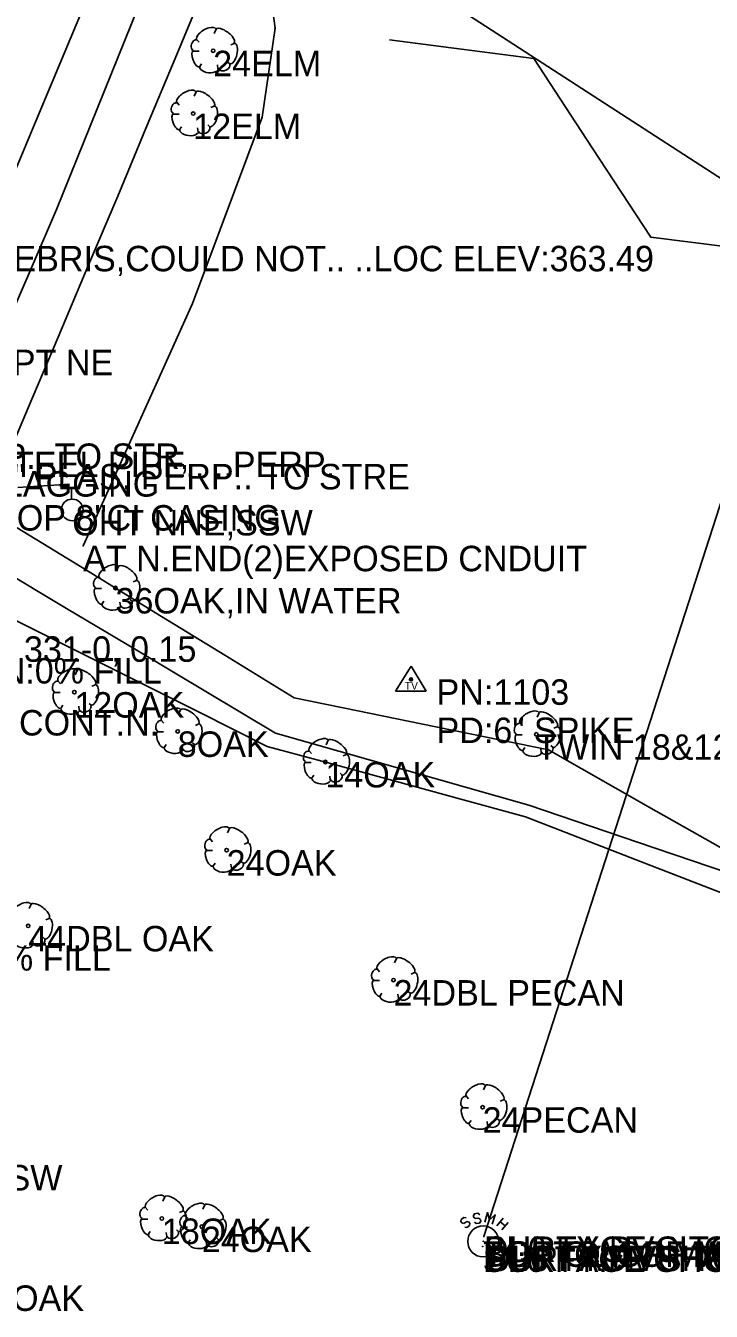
# Model space of a CAD drawing. Extents: x 997398 to 1003416, y 334596 to 337085.
# Drawn here: x 999369.2 to 999503.6, y 335666.7 to 335918.9 of the extents above; entities that cross this region are included whole.
import ezdxf

# ---------------------------------------------------------------- set-up
doc = ezdxf.new("R2010")
doc.units = 0
for name, color, linetype in [('S_EDGE_PAVEMENT', 7, 'Continuous'), ('S_FENCE_ANNOT', 7, 'Continuous'), ('S_FIBER_OPTIC_CABLE', 7, 'Continuous'), ('S_FIBER_OPTIC_CABLE_ANNOT', 7, 'Continuous'), ('S_GRD_PT_SYM', 7, 'Continuous'), ('S_HIST_HIGH_WATER_ANNOT', 7, 'Continuous'), ('S_IRON_PIN_ANNOT', 7, 'Continuous'), ('S_MANHOLE_ANNOT', 7, 'Continuous'), ('S_MISC_TOPO_POINT', 7, 'Continuous'), ('S_PAVEMENT_CROWN', 7, 'Continuous'), ('S_SANITARY_SEWER', 7, 'Continuous'), ('S_SANITARY_SEWER_ANNOT', 7, 'Continuous'), ('S_SECONDARY_CTL', 7, 'Continuous'), ('S_SECONDARY_CTL_ANNOT', 7, 'Continuous'), ('S_SIDE_DRAIN_ANNOT', 7, 'Continuous'), ('S_STREAM', 7, 'Continuous'), ('S_SURVEY_TEXT_ANNOT', 7, 'Continuous'), ('S_TREE', 7, 'Continuous'), ('S_TREE_ANNOT', 7, 'Continuous'), ('S_UTILITY_POLE', 7, 'Continuous'), ('S_UTILITY_POLE_ANNOT', 7, 'Continuous'), ('S_UTL_PT_SYM', 7, 'Continuous'), ('S_WALL', 7, 'Continuous')]:
    doc.layers.add(name, color=color, linetype=linetype)

msp = doc.modelspace()

# ---------------------------------------------------------------- linework, layer by layer
at = {"layer": 'S_EDGE_PAVEMENT'}
for points in [[(999345.79, 335839.7), (999350.09, 335849.94), (999355.27, 335862.25), (999360.45, 335874.56), (999365.63, 335886.87), (999371.17, 335900.18), (999376.72, 335913.48), (999382.27, 335926.79), (999387.81, 335940.1), (999394.44, 335955.02), (999401.06, 335969.95), (999407.69, 335984.87), (999414.31, 335999.8)], [(999431.8, 335993.95), (999426.44, 335980.73), (999421.08, 335967.51), (999415.72, 335954.3), (999410.36, 335941.08), (999404.58, 335927.18), (999398.8, 335913.28), (999393.01, 335899.39), (999387.23, 335885.49), (999381.38, 335871.65), (999375.53, 335857.81), (999369.68, 335843.97), (999364.6, 335831.95)]]:
    msp.add_lwpolyline(points, dxfattribs=at)
at = {"layer": 'S_FIBER_OPTIC_CABLE'}
for p, q in [((999418.06, 335918.42), (999416.18, 335933.11)), ((999415.54, 335900.98), (999418.06, 335918.42)), ((999401.89, 335864.42), (999415.54, 335900.98)), ((999387.01, 335831.35), (999401.89, 335864.42)), ((999380.44, 335816.88), (999387.01, 335831.35))]:
    msp.add_line(p, q, dxfattribs=at)
at = {"layer": 'S_GRD_PT_SYM'}
for points in [[(999458.79, 335679.4), (999458.79, 335679.45), (999458.79, 335679.4), (999458.74, 335679.4), (999458.79, 335679.4), (999458.79, 335679.35), (999458.79, 335679.4), (999458.84, 335679.4)], [(999459, 335681.35), (999459, 335681.4), (999459, 335681.35), (999458.95, 335681.35), (999459, 335681.35), (999459, 335681.3), (999459, 335681.35), (999459.05, 335681.35)], [(999459.5, 335679.55), (999459.5, 335679.6), (999459.5, 335679.55), (999459.45, 335679.55), (999459.5, 335679.55), (999459.5, 335679.5), (999459.5, 335679.55), (999459.55, 335679.55)]]:
    msp.add_lwpolyline(points, dxfattribs=at)
at = {"layer": 'S_PAVEMENT_CROWN'}
msp.add_lwpolyline([(999354.98, 335835.91), (999359.04, 335845.32), (999364.44, 335857.84), (999369.84, 335870.36), (999375.24, 335882.88), (999380.6, 335896.16), (999385.95, 335909.44), (999391.31, 335922.72), (999396.66, 335936.01), (999402.74, 335950.26), (999408.82, 335964.51), (999414.9, 335978.77), (999420.98, 335993.02)], dxfattribs=at)
at = {"layer": 'S_SANITARY_SEWER'}
for p, q in [((999358.9, 335984.04), (999521.53, 335878.51)), ((999459, 335681.35), (999522.12, 335877.02)), ((999454.57, 335684.69), (999454.49, 335684.31)), ((999455.11, 335685.08), (999454.57, 335684.69)), ((999455.54, 335685), (999455.11, 335685.08)), ((999461.54, 335683.45), (999462.78, 335684.93)), ((999454.49, 335684.31), (999454.69, 335684.04)), ((999454.69, 335684.04), (999455.11, 335683.92)), ((999455.11, 335683.92), (999455.65, 335684.27)), ((999455.65, 335683.11), (999455.27, 335683.18)), ((999455.65, 335684.27), (999456.12, 335684.19)), ((999456.2, 335683.49), (999455.65, 335683.11)), ((999456.12, 335684.19), (999456.27, 335683.92)), ((999456.27, 335683.92), (999456.2, 335683.49)), ((999462.2, 335684.23), (999463.17, 335683.42)), ((999463.75, 335684.11), (999462.51, 335682.64))]:
    msp.add_line(p, q, dxfattribs=at)
for points in [[(999458.21, 335685.62), (999457.86, 335685.9), (999457.2, 335685.82), (999456.97, 335685.47), (999457.01, 335685.16), (999457.36, 335684.85), (999457.98, 335684.97), (999458.37, 335684.66), (999458.41, 335684.35), (999458.13, 335683.96), (999457.51, 335683.88), (999457.17, 335684.15)], [(999460.65, 335683.76), (999461.2, 335685.62), (999460.15, 335684.62), (999459.76, 335686.05), (999459.22, 335684.19)]]:
    msp.add_lwpolyline(points, dxfattribs=at)
msp.add_circle((999458.9, 335680.39), 3.05, dxfattribs=at)
at = {"layer": 'S_SECONDARY_CTL'}
for p, q in [((999444.73, 335793.28), (999441.72, 335788.32)), ((999444.73, 335793.28), (999447.67, 335788.32)), ((999441.72, 335788.32), (999447.67, 335788.32))]:
    msp.add_line(p, q, dxfattribs=at)
for radius in [0.311, 0.183, 0.103]:
    msp.add_circle((999444.73, 335790.67), radius, dxfattribs=at)
at = {"layer": 'S_STREAM'}
for points in [[(999331.89, 335832.2), (999349.69, 335826.31), (999367.5, 335820.43), (999381.08, 335812.09), (999394.65, 335803.75), (999408.23, 335795.41), (999421.81, 335787.07), (999434.28, 335784.52), (999446.75, 335781.96), (999459.22, 335779.4), (999471.69, 335776.85), (999491.33, 335765.68), (999510.96, 335754.51)], [(999325.68, 335825.18), (999344.61, 335818.97), (999363.54, 335812.75), (999377.19, 335804.59), (999390.85, 335796.43), (999404.51, 335788.27), (999418.17, 335780.11), (999430.58, 335776.57), (999442.99, 335773.03), (999455.4, 335769.5), (999467.81, 335765.96), (999489.15, 335758.72), (999510.5, 335751.47)], [(999363.15, 335804.23), (999376.49, 335797.55), (999389.84, 335790.87), (999403.19, 335784.2), (999416.53, 335777.52), (999429.2, 335774.06), (999441.86, 335770.61), (999454.53, 335767.16), (999467.19, 335763.7), (999487.73, 335755.71), (999508.28, 335747.72)]]:
    msp.add_lwpolyline(points, dxfattribs=at)
at = {"layer": 'S_TREE'}
for p, q in [((999406.49, 335918.25), (999406.1, 335917.4)), ((999402.69, 335916.24), (999403.2, 335915.66)), ((999410.06, 335915.46), (999409.4, 335915.19)), ((999402.03, 335913.91), (999403.16, 335913.91)), ((999403.2, 335910.74), (999403.66, 335911.43)), ((999409.28, 335911.36), (999408.82, 335911.78)), ((999406.88, 335910.46), (999406.8, 335911.24)), ((999398.78, 335903.91), (999399.29, 335903.32)), ((999402.58, 335905.92), (999402.19, 335905.07)), ((999398.12, 335901.58), (999399.25, 335901.58)), ((999406.15, 335903.13), (999405.49, 335902.86)), ((999399.29, 335898.4), (999399.75, 335899.1)), ((999402.97, 335898.13), (999402.89, 335898.91)), ((999405.37, 335899.02), (999404.91, 335899.45)), ((999383.54, 335810.82), (999384.05, 335810.24)), ((999387.34, 335812.83), (999386.95, 335811.98)), ((999382.89, 335808.49), (999384.01, 335808.49)), ((999390.91, 335810.04), (999390.25, 335809.77)), ((999384.05, 335805.32), (999384.51, 335806.01)), ((999387.73, 335805.04), (999387.65, 335805.82)), ((999390.13, 335805.94), (999389.67, 335806.36)), ((999375.47, 335790.39), (999375.97, 335789.81)), ((999379.27, 335792.4), (999378.88, 335791.55)), ((999374.81, 335788.06), (999375.94, 335788.06)), ((999382.83, 335789.61), (999382.17, 335789.34)), ((999375.97, 335784.89), (999376.44, 335785.58)), ((999379.66, 335784.61), (999379.58, 335785.39)), ((999382.06, 335785.51), (999381.59, 335785.93)), ((999399.54, 335784.7), (999399.15, 335783.84)), ((999469.85, 335784.13), (999469.46, 335783.27)), ((999395.09, 335780.36), (999396.21, 335780.36)), ((999395.74, 335782.68), (999396.25, 335782.1)), ((999403.11, 335781.91), (999402.45, 335781.63)), ((999466.05, 335782.11), (999466.56, 335781.53)), ((999473.41, 335781.34), (999472.76, 335781.07)), ((999396.25, 335777.18), (999396.71, 335777.88)), ((999402.33, 335777.8), (999401.87, 335778.22)), ((999428.49, 335778.71), (999428.1, 335777.85)), ((999465.39, 335779.79), (999466.52, 335779.79)), ((999399.93, 335776.91), (999399.85, 335777.68)), ((999424.69, 335776.69), (999425.2, 335776.11)), ((999432.06, 335775.92), (999431.4, 335775.64)), ((999466.56, 335776.61), (999467.02, 335777.31)), ((999470.24, 335776.34), (999470.16, 335777.11)), ((999472.64, 335777.23), (999472.17, 335777.66)), ((999424.04, 335774.37), (999425.16, 335774.37)), ((999425.2, 335771.19), (999425.66, 335771.89)), ((999428.88, 335770.92), (999428.8, 335771.69)), ((999431.28, 335771.81), (999430.82, 335772.23)), ((999409.12, 335761.41), (999408.74, 335760.55)), ((999405.33, 335759.39), (999405.83, 335758.81)), ((999412.69, 335758.62), (999412.03, 335758.34)), ((999404.67, 335757.07), (999405.79, 335757.07)), ((999405.83, 335753.89), (999406.3, 335754.59)), ((999409.51, 335753.62), (999409.43, 335754.39)), ((999411.91, 335754.51), (999411.45, 335754.93)), ((999370.22, 335746.54), (999369.83, 335745.69)), ((999373.78, 335743.75), (999373.12, 335743.48)), ((999373.01, 335739.64), (999372.54, 335740.07)), ((999370.61, 335738.75), (999370.53, 335739.53)), ((999441.86, 335735.91), (999441.47, 335735.05)), ((999438.06, 335733.89), (999438.57, 335733.31)), ((999445.42, 335733.12), (999444.77, 335732.85)), ((999437.4, 335731.57), (999438.53, 335731.57)), ((999438.57, 335728.39), (999439.03, 335729.09)), ((999442.25, 335728.12), (999442.17, 335728.89)), ((999444.65, 335729.01), (999444.18, 335729.44)), ((999459.33, 335710.96), (999458.94, 335710.11)), ((999455.53, 335708.94), (999456.03, 335708.36)), ((999462.89, 335708.17), (999462.23, 335707.9)), ((999454.87, 335706.62), (999456, 335706.62)), ((999456.03, 335703.44), (999456.5, 335704.14)), ((999459.72, 335703.17), (999459.64, 335703.94)), ((999462.12, 335704.06), (999461.65, 335704.49)), ((999392.63, 335687.11), (999393.13, 335686.53)), ((999396.43, 335689.12), (999396.04, 335688.27)), ((999404.27, 335687.54), (999403.88, 335686.69)), ((999391.97, 335684.78), (999393.1, 335684.78)), ((999399.99, 335686.33), (999399.33, 335686.06)), ((999400.47, 335685.52), (999400.97, 335684.94)), ((999407.83, 335684.75), (999407.17, 335684.48)), ((999393.13, 335681.61), (999393.6, 335682.3)), ((999396.82, 335681.33), (999396.74, 335682.11)), ((999399.22, 335682.23), (999398.75, 335682.65)), ((999399.81, 335683.2), (999400.93, 335683.2)), ((999400.97, 335680.02), (999401.44, 335680.72)), ((999404.65, 335679.75), (999404.58, 335680.52)), ((999407.06, 335680.64), (999406.59, 335681.07))]:
    msp.add_line(p, q, dxfattribs=at)
msp.add_lwpolyline([(999523.83, 335779.4), (999527.91, 335799.55), (999531.98, 335819.7), (999541.56, 335835.34), (999551.14, 335850.97), (999533.12, 335862.72), (999515.1, 335874.46), (999491.75, 335877.42), (999480.27, 335894.95), (999468.8, 335912.48), (999454.65, 335914.32), (999440.5, 335916.16)], dxfattribs=at)
for centre in [(999405.93, 335914.01), (999402.02, 335901.68), (999386.78, 335808.59), (999378.71, 335788.16), (999398.98, 335780.45), (999469.29, 335779.88), (999427.93, 335774.46), (999408.57, 335757.16), (999369.66, 335742.29), (999441.3, 335731.66), (999458.77, 335706.71), (999395.87, 335684.88), (999403.71, 335683.29)]:
    msp.add_circle(centre, 0.341, dxfattribs=at)
for centre, major_axis, ratio, start_param, end_param in [((999404.6, 335917.21), (1.86, 1.08), 0.471018, 0, 3.141593), ((999408.25, 335916.89), (-1.81, 1.36), 0.405113, 3.141593, 6.283186), ((999402.36, 335915.09), (0.31, 1.03), 0.646762, 0, 3.141593), ((999402.67, 335912.44), (-0.61, 1.6), 0.420543, 6.283185, 9.424777), ((999409.61, 335913.48), (0.46, 2.04), 0.482994, 3.141593, 6.283185), ((999408.08, 335910.96), (1.09, 0.46), 0.711534, 3.141592, 6.283185), ((999405.13, 335910.66), (-1.83, 0.19), 0.529943, 0, 3.141593), ((999400.69, 335904.88), (1.86, 1.08), 0.471018, 0, 3.141593), ((999398.45, 335902.76), (0.31, 1.03), 0.646762, 0, 3.141593), ((999404.34, 335904.55), (-1.81, 1.36), 0.405113, 3.141593, 6.283186), ((999398.76, 335900.11), (-0.61, 1.6), 0.420543, 6.283185, 9.424777), ((999405.7, 335901.15), (0.46, 2.04), 0.482994, 3.141593, 6.283185), ((999404.17, 335898.62), (1.09, 0.46), 0.711534, 3.141592, 6.283185), ((999401.22, 335898.33), (-1.83, 0.19), 0.529943, 0, 3.141593), ((999385.45, 335811.79), (1.86, 1.08), 0.471018, 0, 3.141593), ((999389.1, 335811.47), (-1.81, 1.36), 0.405113, 3.141593, 6.283186), ((999383.21, 335809.68), (0.31, 1.03), 0.646762, 0, 3.141593), ((999383.52, 335807.02), (-0.61, 1.6), 0.420543, 6.283185, 9.424777), ((999390.46, 335808.06), (0.46, 2.04), 0.482994, 3.141593, 6.283185), ((999388.94, 335805.54), (1.09, 0.46), 0.711534, 3.141592, 6.283185), ((999385.98, 335805.24), (-1.83, 0.19), 0.529943, 0, 3.141593), ((999377.37, 335791.36), (1.86, 1.08), 0.471018, 0, 3.141593), ((999375.14, 335789.25), (0.31, 1.03), 0.646762, 0, 3.141593), ((999381.03, 335791.04), (-1.81, 1.36), 0.405113, 3.141593, 6.283186), ((999375.44, 335786.59), (-0.61, 1.6), 0.420543, 6.283185, 9.424777), ((999382.38, 335787.63), (0.46, 2.04), 0.482994, 3.141593, 6.283185), ((999380.86, 335785.11), (1.09, 0.46), 0.711534, 3.141592, 6.283185), ((999377.9, 335784.81), (-1.83, 0.19), 0.529943, 0, 3.141593), ((999397.65, 335783.65), (1.86, 1.08), 0.471018, 0, 3.141593), ((999401.3, 335783.33), (-1.81, 1.36), 0.405113, 3.141593, 6.283186), ((999467.95, 335783.08), (1.86, 1.08), 0.471018, 0, 3.141593), ((999471.61, 335782.76), (-1.81, 1.36), 0.405113, 3.141593, 6.283186), ((999395.41, 335781.54), (0.31, 1.03), 0.646762, 0, 3.141593), ((999395.72, 335778.89), (-0.61, 1.6), 0.420543, 6.283185, 9.424777), ((999402.66, 335779.92), (0.46, 2.04), 0.482994, 3.141593, 6.283185), ((999465.72, 335780.97), (0.31, 1.03), 0.646762, 0, 3.141593), ((999472.96, 335779.35), (0.46, 2.04), 0.482994, 3.141593, 6.283185), ((999401.14, 335777.4), (1.09, 0.46), 0.711534, 3.141592, 6.283185), ((999426.6, 335777.66), (1.86, 1.08), 0.471018, 0, 3.141593), ((999430.25, 335777.34), (-1.81, 1.36), 0.405113, 3.141593, 6.283186), ((999466.03, 335778.32), (-0.61, 1.6), 0.420543, 6.283185, 9.424777), ((999398.18, 335777.11), (-1.83, 0.19), 0.529943, 0, 3.141593), ((999424.36, 335775.55), (0.31, 1.03), 0.646762, 0, 3.141593), ((999431.61, 335773.93), (0.46, 2.04), 0.482994, 3.141593, 6.283185), ((999468.49, 335776.54), (-1.83, 0.19), 0.529943, 0, 3.141593), ((999471.44, 335776.83), (1.09, 0.46), 0.711534, 3.141592, 6.283185), ((999424.67, 335772.9), (-0.61, 1.6), 0.420543, 6.283185, 9.424777), ((999427.13, 335771.12), (-1.83, 0.19), 0.529943, 0, 3.141593), ((999430.09, 335771.41), (1.09, 0.46), 0.711534, 3.141592, 6.283185), ((999407.23, 335760.36), (1.86, 1.08), 0.471018, 0, 3.141593), ((999410.88, 335760.04), (-1.81, 1.36), 0.405113, 3.141593, 6.283186), ((999405, 335758.25), (0.31, 1.03), 0.646762, 0, 3.141593), ((999412.24, 335756.63), (0.46, 2.04), 0.482994, 3.141593, 6.283185), ((999405.3, 335755.6), (-0.61, 1.6), 0.420543, 6.283185, 9.424777), ((999407.76, 335753.82), (-1.83, 0.19), 0.529943, 0, 3.141593), ((999410.72, 335754.11), (1.09, 0.46), 0.711534, 3.141592, 6.283185), ((999368.32, 335745.5), (1.86, 1.08), 0.471018, 0, 3.141593), ((999371.98, 335745.17), (-1.81, 1.36), 0.405113, 3.141593, 6.283186), ((999373.33, 335741.76), (0.46, 2.04), 0.482994, 3.141593, 6.283185), ((999368.86, 335738.95), (-1.83, 0.19), 0.529943, 0, 3.141593), ((999371.81, 335739.24), (1.09, 0.46), 0.711534, 3.141592, 6.283185), ((999439.97, 335734.86), (1.86, 1.08), 0.471018, 0, 3.141593), ((999443.62, 335734.54), (-1.81, 1.36), 0.405113, 3.141593, 6.283186), ((999437.73, 335732.75), (0.31, 1.03), 0.646762, 0, 3.141593), ((999444.98, 335731.13), (0.46, 2.04), 0.482994, 3.141593, 6.283185), ((999438.04, 335730.1), (-0.61, 1.6), 0.420543, 6.283185, 9.424777), ((999440.5, 335728.32), (-1.83, 0.19), 0.529943, 0, 3.141593), ((999443.45, 335728.61), (1.09, 0.46), 0.711534, 3.141592, 6.283185), ((999457.43, 335709.91), (1.86, 1.08), 0.471018, 0, 3.141593), ((999461.09, 335709.59), (-1.81, 1.36), 0.405113, 3.141593, 6.283186), ((999455.2, 335707.8), (0.31, 1.03), 0.646762, 0, 3.141593), ((999462.44, 335706.18), (0.46, 2.04), 0.482994, 3.141593, 6.283185), ((999455.5, 335705.15), (-0.61, 1.6), 0.420543, 6.283185, 9.424777), ((999457.97, 335703.37), (-1.83, 0.19), 0.529943, 0, 3.141593), ((999460.92, 335703.66), (1.09, 0.46), 0.711534, 3.141592, 6.283185), ((999394.53, 335688.08), (1.86, 1.08), 0.471018, 0, 3.141593), ((999398.19, 335687.76), (-1.81, 1.36), 0.405113, 3.141593, 6.283186), ((999392.3, 335685.96), (0.31, 1.03), 0.646762, 0, 3.141593), ((999402.37, 335686.49), (1.86, 1.08), 0.471018, 0, 3.141593), ((999406.03, 335686.17), (-1.81, 1.36), 0.405113, 3.141593, 6.283186), ((999392.61, 335683.31), (-0.61, 1.6), 0.420543, 6.283185, 9.424777), ((999399.54, 335684.35), (0.46, 2.04), 0.482994, 3.141593, 6.283185), ((999400.14, 335684.38), (0.31, 1.03), 0.646762, 0, 3.141593), ((999407.38, 335682.76), (0.46, 2.04), 0.482994, 3.141593, 6.283185), ((999398.02, 335681.83), (1.09, 0.46), 0.711534, 3.141592, 6.283185), ((999400.44, 335681.73), (-0.61, 1.6), 0.420543, 6.283185, 9.424777), ((999395.07, 335681.53), (-1.83, 0.19), 0.529943, 0, 3.141593), ((999402.9, 335679.95), (-1.83, 0.19), 0.529943, 0, 3.141593), ((999405.86, 335680.24), (1.09, 0.46), 0.711534, 3.141592, 6.283185)]:
    msp.add_ellipse(centre, major_axis=major_axis, ratio=ratio, start_param=start_param, end_param=end_param, dxfattribs=at)
at = {"layer": 'S_UTILITY_POLE'}
msp.add_line((999378.16, 335826.04), (999378.16, 335828.15), dxfattribs=at)
msp.add_circle((999378.29, 335823.9), 2.13, dxfattribs=at)
at = {"layer": 'S_UTL_PT_SYM'}
for points in [[(999418.06, 335918.42), (999418.06, 335918.47), (999418.06, 335918.42), (999418.01, 335918.42), (999418.06, 335918.42), (999418.06, 335918.37), (999418.06, 335918.42), (999418.11, 335918.42)], [(999415.54, 335900.98), (999415.54, 335901.03), (999415.54, 335900.98), (999415.49, 335900.98), (999415.54, 335900.98), (999415.54, 335900.93), (999415.54, 335900.98), (999415.59, 335900.98)], [(999401.89, 335864.42), (999401.89, 335864.47), (999401.89, 335864.42), (999401.84, 335864.42), (999401.89, 335864.42), (999401.89, 335864.37), (999401.89, 335864.42), (999401.94, 335864.42)], [(999387.01, 335831.35), (999387.01, 335831.4), (999387.01, 335831.35), (999386.96, 335831.35), (999387.01, 335831.35), (999387.01, 335831.3), (999387.01, 335831.35), (999387.06, 335831.35)], [(999380.44, 335816.88), (999380.44, 335816.93), (999380.44, 335816.88), (999380.39, 335816.88), (999380.44, 335816.88), (999380.44, 335816.83), (999380.44, 335816.88), (999380.49, 335816.88)], [(999458.79, 335679.4), (999458.79, 335679.45), (999458.79, 335679.4), (999458.74, 335679.4), (999458.79, 335679.4), (999458.79, 335679.35), (999458.79, 335679.4), (999458.84, 335679.4)], [(999458.9, 335680.39), (999458.9, 335680.44), (999458.9, 335680.39), (999458.85, 335680.39), (999458.9, 335680.39), (999458.9, 335680.34), (999458.9, 335680.39), (999458.95, 335680.39)], [(999459, 335681.35), (999459, 335681.4), (999459, 335681.35), (999458.95, 335681.35), (999459, 335681.35), (999459, 335681.3), (999459, 335681.35), (999459.05, 335681.35)], [(999459.5, 335679.55), (999459.5, 335679.6), (999459.5, 335679.55), (999459.45, 335679.55), (999459.5, 335679.55), (999459.5, 335679.5), (999459.5, 335679.55), (999459.55, 335679.55)]]:
    msp.add_lwpolyline(points, dxfattribs=at)
at = {"layer": 'S_WALL'}
msp.add_lwpolyline([(999367.62, 335828.3), (999377.79, 335828.97)], dxfattribs=at)

# ---------------------------------------------------------------- texts
at = {"layer": 'S_FENCE_ANNOT'}
msp.add_text('JOINS ANGLE PT NE', height=5, dxfattribs=at).set_placement((999320.58, 335850.35))
at = {"layer": 'S_FIBER_OPTIC_CABLE_ANNOT'}
for s, p in [('AT N.END(2)EXPOSED CNDUIT', (999380.44, 335811.88)), ('CONT.N.', (999367.86, 335779.65))]:
    msp.add_text(s, height=5, dxfattribs=at).set_placement(p)
at = {"layer": 'S_HIST_HIGH_WATER_ANNOT'}
msp.add_text('TOP OF DEBRIS,COULD NOT.. ..LOC ELEV:363.49', height=5, dxfattribs=at).set_placement((999335.19, 335870.73))
at = {"layer": 'S_IRON_PIN_ANNOT'}
msp.add_text('TPOST W/ FLAGGING', height=5, dxfattribs=at).set_placement((999326.64, 335826.52))
at = {"layer": 'S_MANHOLE_ANNOT'}
msp.add_text('BOTTOM OF MANHOLE', height=5, dxfattribs=at).set_placement((999458.9, 335675.39))
at = {"layer": 'S_MISC_TOPO_POINT'}
for p in [(999458.79, 335674.4), (999459, 335676.35), (999459.5, 335674.55)]:
    msp.add_text('SURFACE SHOT FOR UG PIPE', height=5, dxfattribs=at).set_placement(p)
at = {"layer": 'S_SANITARY_SEWER_ANNOT'}
for s, p in [('TOP CL OF MANHOLE', (999458.9, 335675.39)), ('DI:6 TY:PVC', (999458.79, 335674.4)), ('DI:6 TY:PVC TO NNE', (999459, 335676.35)), ('DI:6 TY:PVC TO SE', (999459.5, 335674.55))]:
    msp.add_text(s, height=5, dxfattribs=at).set_placement(p)
at = {"layer": 'S_SECONDARY_CTL'}
msp.add_text('TV', height=1.5, rotation=360, dxfattribs=at).set_placement((999443.52, 335788.66))
at = {"layer": 'S_SECONDARY_CTL_ANNOT'}
for s, p in [('PN:1103', (999449.73, 335785.67)), ('PD:6" SPIKE', (999449.73, 335778.17))]:
    msp.add_text(s, height=5, dxfattribs=at).set_placement(p)
at = {"layer": 'S_SIDE_DRAIN_ANNOT'}
for s, p in [('DI:15 TY:CMP CN:0% FILL', (999314.48, 335789.85)), ('DI:26 DI:24 TY:CPP CN:0% FILL', (999287.77, 335733.51))]:
    msp.add_text(s, height=5, dxfattribs=at).set_placement(p)
at = {"layer": 'S_SURVEY_TEXT_ANNOT'}
for s, p in [('TOP 12"CI CASING,PERP.. TO STR,', (999289.63, 335831.95)), ('EXPOSED 3" STEEL PIPE.. ..PERP.', (999320.1, 335830.34)), ('EXPOSED 3" PLAS, PERP.. TO STRE', (999328.8, 335827.94)), ('TOP 8"CI CASING TOP 8"CI CASING', (999305.61, 335819.86)), ('SN: 331-0, 0.15', (999355.82, 335794.11))]:
    msp.add_text(s, height=5, dxfattribs=at).set_placement(p)
at = {"layer": 'S_TREE_ANNOT'}
for s, p in [('24ELM', (999405.93, 335909.01)), ('12ELM', (999402.02, 335896.68)), ('36OAK,IN WATER', (999386.78, 335803.59)), ('12OAK', (999378.71, 335783.16)), ('8OAK', (999398.98, 335775.45)), ('TWIN 18&12OAK', (999469.29, 335774.88)), ('14OAK', (999427.93, 335769.46)), ('24OAK', (999408.57, 335752.16)), ('44DBL OAK', (999369.66, 335737.29)), ('24DBL PECAN', (999441.3, 335726.66)), ('24PECAN', (999458.77, 335701.71)), ('18OAK', (999395.87, 335679.88)), ('24OAK', (999403.71, 335678.29)), ('36OAK', (999359.06, 335666.75))]:
    msp.add_text(s, height=5, dxfattribs=at).set_placement(p)
at = {"layer": 'S_UTILITY_POLE_ANNOT'}
for p in [(999378.29, 335818.9), (999329.2, 335690.38)]:
    msp.add_text('OHT NNE,SSW', height=5, dxfattribs=at).set_placement(p)

doc.saveas('drawing.dxf')
